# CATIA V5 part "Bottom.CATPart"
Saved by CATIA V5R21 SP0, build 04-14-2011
Part number: Part1.2
Material "DS Red": density 7860 kg/m3, Young's modulus 2e+11 Pa, Poisson ratio 0.266
Bounding box of the stored display mesh (mm): x 0 to 10, y -50 to 50, z -15 to 15
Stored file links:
  G:\CATIA\Class\Project_2\Bottom.CATPart
  C:\Program Files (x86)\Dassault Systemes\B21\intel_a\startup\materials\Catalog.CATMaterial
  C:\Program Files (x86)\Dassault Systemes\B21\intel_a\startup\materials\red_env_512x512.jpg
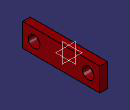
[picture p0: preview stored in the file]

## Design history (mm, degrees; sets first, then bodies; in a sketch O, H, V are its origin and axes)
Body1 (main body), material "DS Red"
  Sketch1 on yz-plane, origin (0, 0, 0), H (0, 1, 0), V (0, 0, 1)
    line L1 (50, 15) -> (50, -15)
    line L2 (50, -15) -> (-50, -15)
    line L3 (-50, -15) -> (-50, 15)
    line L4 (-50, 15) -> (50, 15)
    length L4 = 100
    length L3 = 30
    vertical: L1 V, L3 V
    horizontal: L2 H, L4 H
    equidistance: L1 L3 O, L2 L4 O
  Pad1: profile Sketch1, direction (1, 0, 0), length 10
  Sketch2 on end face of Pad1, origin (10, 0, 0), H (0, 1, 0), V (0, 0, 1)
    circle A1 centre (35, 0) radius 7.5
    point P1 (35, 0)
    reference projected line E1 (50, -15) -> (50, 15) from edge [face of Pad1 from Sketch1.L1 | end face of Pad1]
    circle A2 centre (-35, 0) radius 7.5
    radius A1 = 7.5
    distance P1 E1 = 15
    coincidence: H P1
    symmetry: A1 A2 V
  Pocket1: profile Sketch2, direction (-1, 0, 0), length 10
